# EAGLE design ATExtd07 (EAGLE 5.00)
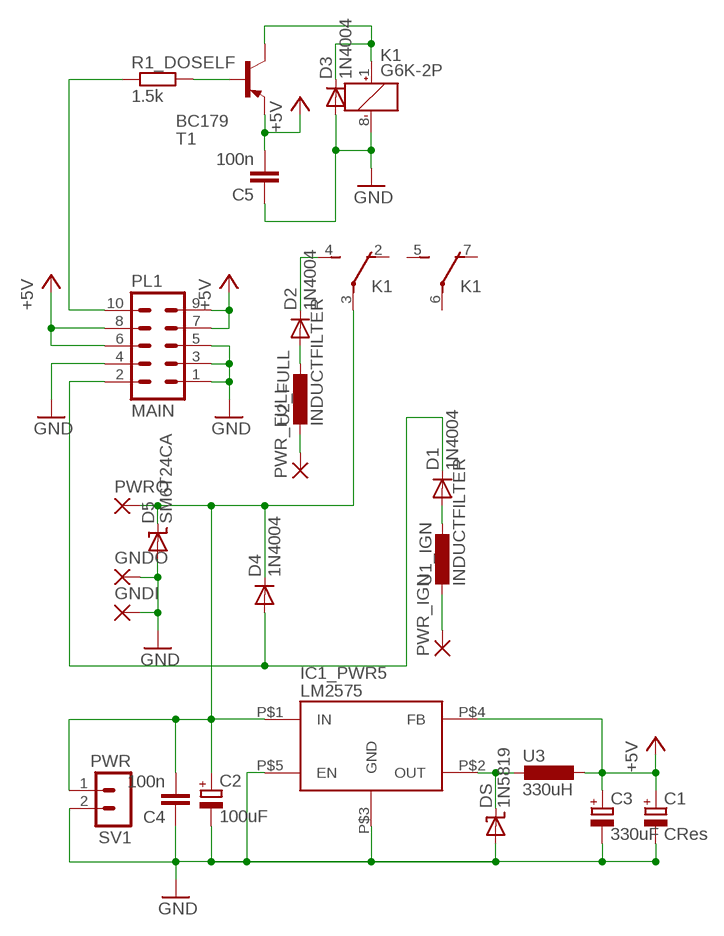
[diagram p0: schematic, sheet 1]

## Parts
C1  CRes  CPOL-EUE2-5  [E2-5]
C2  100uF  CPOL-EUE5-8.5  [E5-8,5]
C3  330uF  CPOL-EUE5-8.5  [E5-8,5]
C4  100n  C-EU025-025X050  [C025-025X050]
C5  100n  C-EU025-025X050  [C025-025X050]
D1  1N4004  [DO41-10]
D2  1N4004  [DO41-10]
D3  1N4004  [DO41-10]
D4  1N4004  [DO41-10]
D5  SM6T24CA  TRANSIL  [SOD15]
DS  1N5819  [DOS]
GNDI  2,54/1,0  [2,54/1,0]
GNDO  2,54/1,0  [2,54/1,0]
IC1_PWR5  LM2575  [TO220-5PIN-1]
K1  G6K-2P  [G6K-2P]
PL1  MAIN  10V  [10V]
PWR_FULL  2,54/1,0  [2,54/1,0]
PWR_IGN  2,54/1,0  [2,54/1,0]
PWRO  2,54/1,0  [2,54/1,0]
R1_DOSELF  1.5k  R-EU_0309/10  [0309/10]
SV1  PWR  MA02-1  [MA02-1]
T1  BC179  [TO18]
U1_IGN  INDUCTFILTER  [INDUCT]
U2_FULL  INDUCTFILTER  [INDUCT]
U3  330uH  INDUCTPOWER2SMD  [PISR]

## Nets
+5V: C1.+ C3.+ C5.2 IC1_PWR5.P$4(FB) PL1.6 PL1.7 PL1.8 PL1.9 T1.1(E) U3.P$1
GND: C1.- C2.- C3.- C4.1 C5.1 D3.A D5.P$2(A) DS.A GNDI.1(P) GNDO.1(P) IC1_PWR5.P$3(GND) IC1_PWR5.P$5(EN) K1.8(1:-) PL1.1 PL1.3 PL1.4 PL1.5 SV1.2
N$3: D1.C D4.A PL1.2
N$7: PWR_FULL.1(P) U2_FULL.2
N$19: C2.+ C4.2 D4.C D5.P$1(C) IC1_PWR5.P$1(IN) K1.3(2:P) PWRO.1(P) SV1.1
N$25: D2.C K1.4(2:S)
N$26: PWR_IGN.1(P) U1_IGN.2
N$27: D1.A U1_IGN.1
N$28: D2.A U2_FULL.1
N$30: PL1.10 R1_DOSELF.1
N$32: R1_DOSELF.2 T1.2(B)
N$52: DS.C IC1_PWR5.P$2(OUT) U3.P$2
N$65: D3.C K1.1(1:+) T1.3(C)
Unconnected: K1.2(2:O) K1.5(3:S) K1.6(3:P) K1.7(3:O)

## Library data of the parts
C1-C3 = smf:CPOL-EU: POLARIZED CAPACITOR, European symbol
C4 C5 = smf:C-EU: CAPACITOR, European symbol
D1-D4 = smf:1N4004: DIODE
D5 = smf:TRANSIL
DS = smf:1N5819
GNDI GNDO PWR_FULL PWR_IGN PWRO = smf:2,54/1,0: THROUGH-HOLE PAD
IC1_PWR5 = smf:LM2575
K1 = smf:G6K: Low Signal Relay oeiwcsnts1.omron.com/.. D20G6K0100.pdf
PL1 = smf:10V: CONNECTOR
R1_DOSELF = smf:R-EU_: RESISTOR, European symbol
SV1 = smf:MA02-1
T1 = smf:BC179: PNP Transistor
U1_IGN U2_FULL U3 = smf:INDUCT

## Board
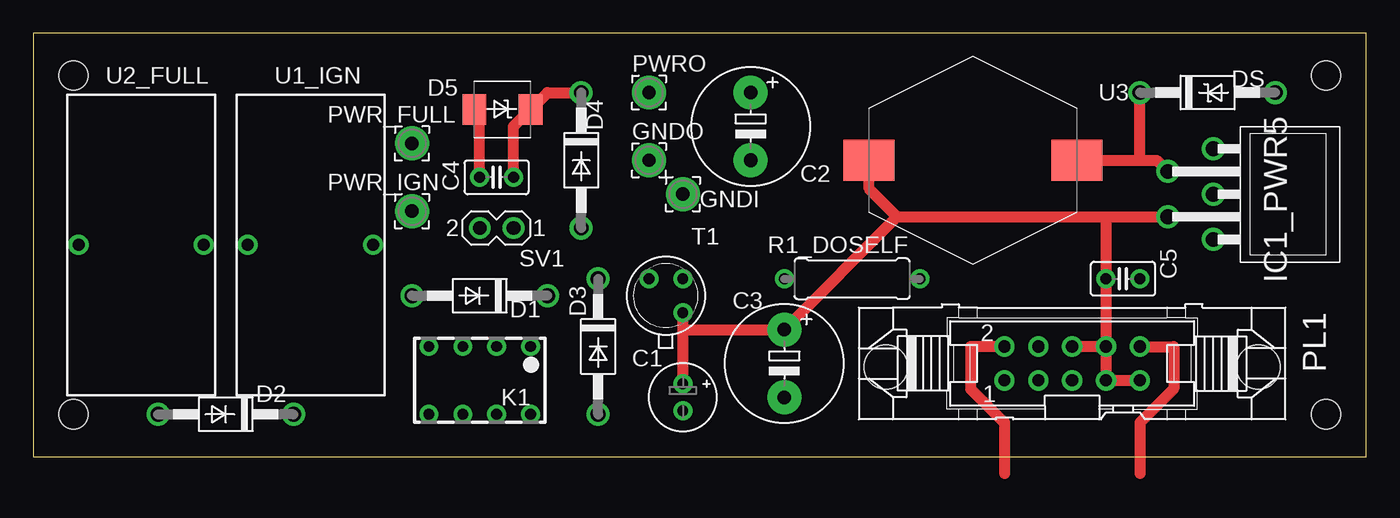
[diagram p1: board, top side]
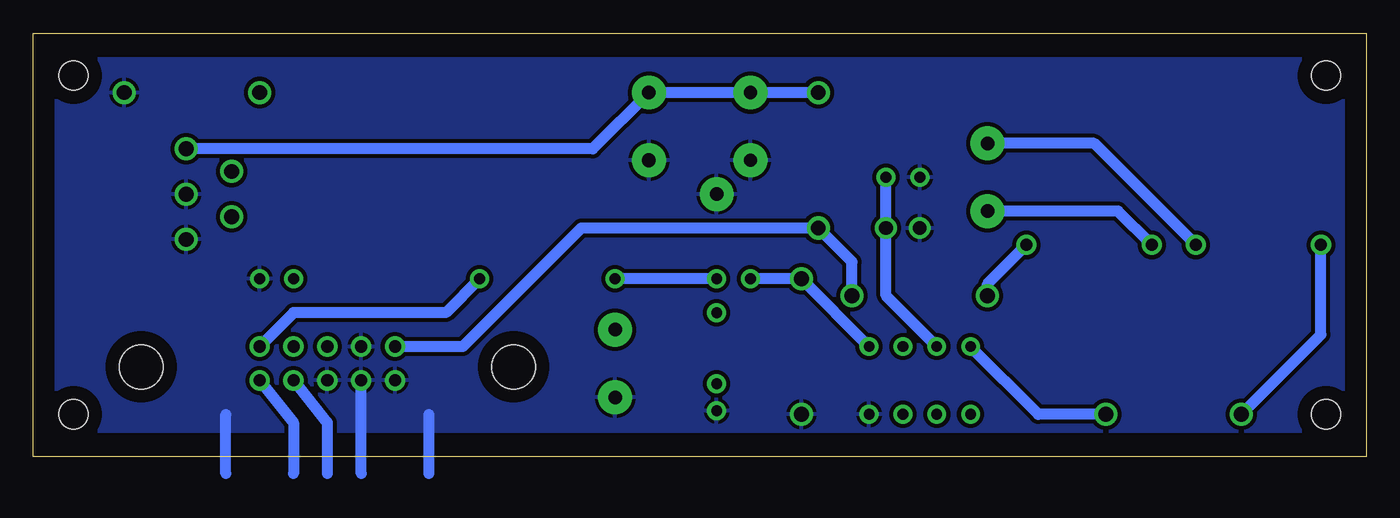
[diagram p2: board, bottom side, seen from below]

Size 100 x 31.74 mm. Coordinates in mm from the lower left corner, seen from the top.
Outline: 0,0 100,0 100,31.74 0,31.74 0,0
Copper layers (1*16): Top 0.035mm / dielectric 1.5mm / Bottom 0.035mm
Design rules "default *": minimum track width 16mil, minimum drill 24mil, track to track 12mil, track to pad 12mil, pad to pad 12mil, via to via 12mil, smd to smd 8mil, copper to edge 40mil, drill to drill 12mil, minimum pad ring 12mil, minimum via ring 8mil, stop-mask expansion 4mil, vias tented up to drill 0mil, thermal gap 10mil
Holes 2.2 mm at 3.01,3.17 96.99,3.17 96.99,28.57 3.01,28.57

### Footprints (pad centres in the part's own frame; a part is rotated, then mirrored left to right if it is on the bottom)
E2-5 = drill 0.813 pad 1.27 round: + -1.016,0; - 1.016,0
E5-8,5 = drill 1.016 pad 2.54 round: + -2.54,0; - 2.54,0
C025-025X050 = drill 0.813 round: 1 -1.27,0; 2 1.27,0
DO41-10 = drill 1.118 round: A 5.08,0; C -5.08,0
SOD15 = smd 1.778 x 2.286: P$1 0,0; P$2 4.22,0
DOS = drill 1.118 round: A 5.08,0; C -5.08,0
2,54/1,0 = drill 1 pad 2.54 round: 1 0,0
TO220-5PIN-1 = drill 1.118 round: P$1 -3.4,1.7; P$2 -1.7,-1.7; P$3 0,1.7; P$4 1.7,-1.7; P$5 3.4,1.7
G6K-2P = drill 0.8 round: 1 -2.54,-2.54; 2 0,-2.54; 3 2.54,-2.54; 4 5.08,-2.54; 5 5.08,2.54; 6 2.54,2.54; 7 0,2.54; 8 -2.54,2.54
10V = drill 0.914 round: 1 -5.08,-1.27; 2 -5.08,1.27; 3 -2.54,-1.27; 4 -2.54,1.27; 5 0,-1.27; 6 0,1.27; 7 2.54,-1.27; 8 2.54,1.27; 9 5.08,-1.27; 10 5.08,1.27 | hole 3.302: 13.97,-0.254; -13.97,-0.254
0309/10 = drill 0.813 round: 1 -5.08,0; 2 5.08,0
MA02-1 = drill 1.016 round: 1 -1.27,0; 2 1.27,0
TO18 = drill 0.813 round: 1 -1.27,-1.27; 2 1.27,-1.27; 3 1.27,1.27
INDUCT = drill 0.9 round: 1 -4.7,0; 2 4.7,0
PISR = smd 3.81 x 3.048: P$1 0,0; P$2 15.6,0

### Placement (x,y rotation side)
C1  48.73,4.44 270 top
C2  53.81,24.76 270 top
C3  56.35,6.98 270 top
C4  34.76,20.95 0 top
C5  81.75,13.33 180 top
D1  33.49,12.06 180 top
D2  14.44,3.17 180 top
D3  42.38,8.25 270 top
D4  41.11,22.22 270 top
D5  37.3,26.03 180 top
DS  88.1,27.3 0 top
GNDI  48.73,19.68 0 top
GNDO  46.19,22.22 0 top
IC1_PWR5  86.83,19.68 270 top
K1  34.76,5.71 180 top
PL1  77.94,6.98 0 top
PWR_FULL  28.41,23.49 0 top
PWR_IGN  28.41,18.41 0 top
PWRO  46.19,27.3 0 top
R1_DOSELF  61.43,13.33 180 top
SV1  34.76,17.14 180 top
T1  47.46,12.06 90 top
U1_IGN  20.79,15.87 180 top
U2_FULL  8.09,15.87 0 top
U3  62.7,22.22 0 top

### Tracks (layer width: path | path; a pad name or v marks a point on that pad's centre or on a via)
+5V
  Top 0.813: 64.81,17.98 80.48,17.98 | 80.48,17.98 IC1_PWR5.P$4 | 64.81,17.98 C3.+ 48.73,9.52 | 64.81,17.98 62.7,20.09 U3.P$1 | 80.48,17.98 C5.2 PL1.8 | PL1.8 PL1.7 PL1.9 | PL1.8 PL1.6 | C1.+ 48.73,9.52 | 48.73,9.52 T1.1
  Bottom 0.813: PL1.7 77.94,2.54 77.94,-1.27 | PL1.9 80.48,2.54 80.48,-1.27
GND
  Top 0.813: D5.P$2 33.49,25.62 C4.1
  Bottom 0.813: 75.4,-1.27 PL1.3 | 70.32,-1.27 70.32,3.17 | 85.56,-1.27 85.56,3.17
  pour Bottom (isolate 0.305): 1.74,29.84 1.74,1.9 98.26,1.9 98.26,29.84
N$3
  Top 0.813: PL1.2 70.32,8.25 70.32,5.08 72.86,2.54 72.86,-1.27
  Bottom 0.813: PL1.2 67.78,8.25 58.89,17.14 D4.A 38.57,14.6 D1.C
N$7
  Bottom 0.813: U2_FULL.2 20.41,23.49 PWR_FULL.1
N$19
  Top 0.813: C4.2 36.03,24.76 D5.P$1 38.57,27.3 D4.C
  Bottom 0.813: D4.C PWRO.1 C2.+ 58.03,23.08 IC1_PWR5.P$1 | C4.2 SV1.1 36.03,12.06 K1.3
N$25
  Bottom 0.813: D2.C 24.6,3.17 K1.4
N$26
  Bottom 0.813: U1_IGN.2 18.63,18.41 PWR_IGN.1
N$27
  Bottom 0.813: U1_IGN.1 28.41,12.95 D1.A
N$28
  Bottom 0.813: U2_FULL.1 3.39,9.14 D2.A
N$30
  Top 0.813: PL1.10 85.56,8.25 85.56,5.08 83.02,2.54 83.02,-1.27
  Bottom 0.813: R1_DOSELF.1 69.05,10.79 80.48,10.79 PL1.10
N$32
  Bottom 0.813: T1.2 R1_DOSELF.2
N$52
  Top 0.813: 77.94,22.22 U3.P$2 83.02,22.22 | IC1_PWR5.P$2 84.29,22.22 83.02,22.22 | 83.02,22.22 DS.C
N$65
  Bottom 0.813: T1.3 D3.C K1.1

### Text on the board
tDocu: smfATDemoExtd1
